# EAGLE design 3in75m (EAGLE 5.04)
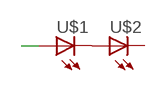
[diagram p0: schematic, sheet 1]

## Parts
U$1  LEDSMT1206  [1206]
U$2  LEDSMT1206  [1206]

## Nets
N$1: U$1.A
N$3: U$1.C U$2.A
Unconnected: U$2.C

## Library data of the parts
U$1 U$2 = led(2):LED: LED

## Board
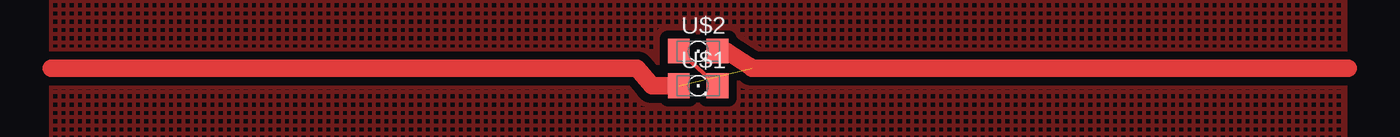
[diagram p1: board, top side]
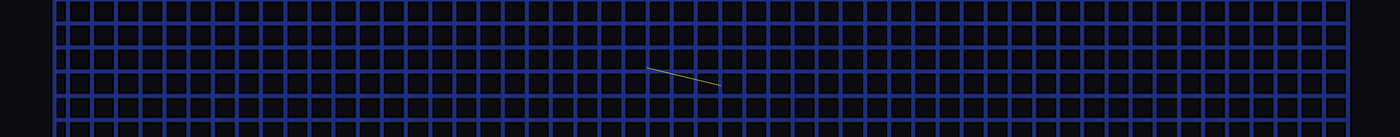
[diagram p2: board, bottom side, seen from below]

No outline drawn. Coordinates in mm, seen from the top.
Copper layers (1*16): Top 0.035mm / dielectric 1.5mm / Bottom 0.035mm
Design rules "default": minimum track width 10mil, minimum drill 24mil, track to track 8mil, track to pad 8mil, pad to pad 8mil, via to via 8mil, smd to smd 8mil, copper to edge 40mil, drill to drill 8mil, minimum pad ring 10mil, minimum via ring 8mil, stop-mask expansion 4mil, vias tented up to drill 0mil, thermal gap 10mil

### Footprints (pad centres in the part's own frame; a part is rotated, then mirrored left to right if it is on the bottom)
1206 = smd 1.6 x 1.803: A -1.422,0; C 1.422,0

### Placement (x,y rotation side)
U$1  47.62,11.43 0 top
U$2  47.62,13.97 0 top

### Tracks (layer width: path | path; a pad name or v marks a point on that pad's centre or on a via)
N$1  (1 unrouted)
  Top 1.27: 51.58,12.7 95.48,12.7 | U$1.A 44.21,11.43 43.14,12.7 0,12.7
N$2
  pour Top (isolate 0.61, hatched): 0,25.4 95.25,25.4 95.25,0 0,0
  pour Bottom (isolate 0.61, hatched): 0,25.4 95.25,25.4 95.25,0 0,0
N$3
  Top 0.305: U$1.C U$2.A
N$4
  Top 1.27: 49.71,13.97 51.38,12.9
